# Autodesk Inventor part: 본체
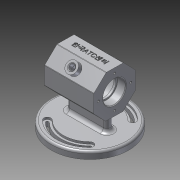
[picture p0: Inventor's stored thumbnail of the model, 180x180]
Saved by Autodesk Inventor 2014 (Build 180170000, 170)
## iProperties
Created: 2017-06
Part Number: 본체
Material: 알루미늄 6061
Document SubType Name: Modeling
Designer: Administrator
Density: 2.71 g/cm^3
Appearance: 알루미늄 - 평지
Mass: 555.742 g
Surface Area: 568.044 cm^2
Volume: 205.071 cm^3
Author: Administrator
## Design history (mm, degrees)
sketch "스케치1"
  geometry: C1 r 55 at (0, 0); 1 further point
  constraints: 1 centre point, 1 coincident
  dimensions: "d0" = 110 diameter of C1
extrude "돌출1" new body sketch "스케치1" distance "d1" = 10; taper "d2" = 0 deg
sketch "스케치2"
  geometry: L1 (0, 0)-(-33.941, 33.941); L2 (0, 0)-(48, 0); L3 (0, 0)-(33.941, 33.941); L4 (0, 0)-(48, 0); L5 (0, 0)-(-33.941, -33.941); L6 (0, 0)-(48, 0); L7 (0, 0)-(33.941, -33.941); L8 (0, 0)-(48, 0); C1 r 5 at (30.406, 30.406); C2 r 5 at (-30.406, -30.406); C3 r 5 at (30.406, -30.406); A1 r 38 centre (0, 0) between (-26.87, -26.87) and (26.87, -26.87); A2 r 38 centre (0, 0) between (26.87, 26.87) and (-26.87, 26.87); A3 r 48 centre (0, 0) between (-33.941, -33.941) and (33.941, -33.941); A4 r 48 centre (0, 0) between (33.941, 33.941) and (-33.941, 33.941); A5 r 5 centre (-30.406, 30.406) between (-33.941, 33.941) and (-26.87, 26.87)
  constraints: 16 end point, 10 point on circle, 8 centre point, 4 equal length, 4 horizontal, 4 point on line, 1 coincident
  dimensions: "d6" = 135 deg angle of L2 L1; "d7" = 45 deg angle of L4 L3; "d8" = 135 deg angle of L5 L6; "d9" = 45 deg angle of L7 L8; "d10" = 10 diameter of A5; "d11" = 10 diameter of C1; "d12" = 10 diameter of C2; "d13" = 10 diameter of C3
extrude "돌출2" cut sketch "스케치2" distance "d14" = 3; taper "d15" = 0 deg
sketch "스케치3"
  geometry: C1 r 55 at (0, 0) reference; A1 r 5 centre (-30.406, -30.406) between (-26.87, -26.87) and (-33.941, -33.941) reference; A2 r 5 centre (30.406, -30.406) between (33.941, -33.941) and (26.87, -26.87) reference; A3 r 5 centre (30.406, 30.406) between (26.87, 26.87) and (33.941, 33.941) reference; A4 r 5 centre (-30.406, 30.406) between (-33.941, 33.941) and (-26.87, 26.87) reference; A5 r 2 centre (-30.406, 30.406) between (-31.82, 31.82) and (-28.991, 28.991); A6 r 2 centre (30.406, 30.406) between (28.991, 28.991) and (31.82, 31.82); A7 r 2 centre (-30.406, -30.406) between (-28.991, -28.991) and (-31.82, -31.82); A8 r 41 centre (0, 0) between (-28.991, -28.991) and (28.991, -28.991); A9 r 41 centre (0, 0) between (28.991, 28.991) and (-28.991, 28.991); A10 r 45 centre (0, 0) between (-31.82, -31.82) and (31.82, -31.82); A11 r 45 centre (0, 0) between (31.82, 31.82) and (-31.82, 31.82); A12 r 2 centre (30.406, -30.406) between (28.991, -28.991) and (31.82, -31.82)
  constraints: 16 point on circle, 8 centre point, 6 coincident
  dimensions: "d16" = 4 diameter of A5; "d17" = 4 diameter of A6; "d18" = 4 diameter of A7; "d21" = 4 diameter of A12
extrude "돌출3" cut sketch "스케치3" stored distance "d22" = 3; taper "d23" = 0 deg
sketch "스케치4"
  geometry: L1 (24, 5)-(-24, 5); L2 (-24, 5)-(-24, -5); L3 (-24, -5)-(24, -5); L4 (24, -5)-(24, 5); L5 (24, 5)-(-24, -5); L6 (-24, 5)-(24, -5); C1 r 55 at (0, 0) reference; C2 r 5 at (-24, 0); C3 r 5 at (24, 0)
  constraints: 12 end point, 4 midpoint, 2 centre point, 2 parallel, 1 horizontal, 1 perpendicular
  dimensions: "d24" = 48 distance between parallel lines of L4 L2; "d25" = 10 distance between parallel lines of L3 L1; "d26" = 10 diameter of C2; "d27" = 10 diameter of C3
extrude "돌출4" join sketch "스케치4" distance "d28" = 52; taper "d29" = 0 deg
node "작업 평면1"
sketch "스케치5"
  geometry: L1 (38, 10)-(38, 7) reference; L2 (38, 7)-(41, 7) reference; L3 (41, 7)-(41, 0) reference; L4 (41, 0)-(-41, 0) reference; L5 (-41, 0)-(-41, 7) reference; L6 (-41, 7)-(-38, 7) reference; L7 (-38, 7)-(-38, 10) reference; L8 (-38, 10)-(-5, 10) reference; L9 (-5, 10)-(-5, 62) reference; L10 (-5, 62)-(5, 62) reference; L11 (5, 62)-(5, 10) reference; L12 (5, 10)-(38, 10) reference; L13 (-55, 0)-(-55, 10) reference; L14 (-55, 10)-(-48, 10) reference; L15 (-48, 10)-(-48, 7) reference; L16 (-48, 7)-(-45, 7) reference; L17 (-45, 7)-(-45, 0) reference; L18 (-45, 0)-(-55, 0) reference; L19 (55, 10)-(55, 0) reference; L20 (55, 0)-(45, 0) reference; L21 (45, 0)-(45, 7) reference; L22 (45, 7)-(48, 7) reference; L23 (48, 7)-(48, 10) reference; L24 (48, 10)-(55, 10) reference; L25 (-11.904, 92)-(12.795, 91.631); L26 (12.795, 91.631)-(30, 73.904); L27 (30, 73.904)-(29.631, 49.205); L28 (29.631, 49.205)-(11.904, 32); L29 (11.904, 32)-(-12.795, 32.369); L30 (-12.795, 32.369)-(-30, 50.096); L31 (-30, 50.096)-(-29.631, 74.795); L32 (-29.631, 74.795)-(-11.904, 92); 2 further points
  constraints: 16 end point, 17 other
extrude "돌출5" join sketch "스케치5" stored distance "d32" = 70; taper "d33" = 0 deg
node "작업 평면2"
sketch "스케치6"
  geometry: L1 (38, 10)-(38, 7) reference; L2 (38, 7)-(41, 7) reference; L3 (41, 7)-(41, 0) reference; L4 (41, 0)-(-41, 0) reference; L5 (-41, 0)-(-41, 7) reference; L6 (-41, 7)-(-38, 7) reference; L7 (-38, 7)-(-38, 10) reference; L8 (-38, 10)-(-5, 10) reference; L9 (-5, 10)-(-5, 32.253) reference; L10 (-5, 32.253)-(-12.795, 32.369) reference; L11 (-12.795, 32.369)-(-30, 50.096) reference; L12 (-30, 50.096)-(-29.631, 74.795) reference; L13 (-29.631, 74.795)-(-11.904, 92) reference; L14 (-11.904, 92)-(12.795, 91.631) reference; L15 (12.795, 91.631)-(30, 73.904) reference; L16 (30, 73.904)-(29.631, 49.205) reference; L17 (29.631, 49.205)-(11.904, 32) reference; L18 (11.904, 32)-(5, 32.103) reference; L19 (5, 32.103)-(5, 10) reference; L20 (5, 10)-(38, 10) reference; L21 (-55, 0)-(-55, 10) reference; L22 (-55, 10)-(-48, 10) reference; L23 (-48, 10)-(-48, 7) reference; L24 (-48, 7)-(-45, 7) reference; L25 (-45, 7)-(-45, 0) reference; L26 (-45, 0)-(-55, 0) reference; L27 (55, 10)-(55, 0) reference; L28 (55, 0)-(45, 0) reference; L29 (45, 0)-(45, 7) reference; L30 (45, 7)-(48, 7) reference; L31 (48, 7)-(48, 10) reference; L32 (48, 10)-(55, 10) reference; L33 (21.087, 40.913)-(-26.038, 88.038); L34 (-26.829, 77.515)-(-21.087, 83.087); L35 (-31.779, 82.465)-(-26.038, 88.038); L36 (15.346, 35.34)-(-31.779, 82.465); L37 (-31.779, 82.465)-(-5.657, 56.343); 1 further point
  constraints: 10 end point, 4 point on line, 2 parallel, 1 collinear
  dimensions: "d36" = 7 distance between parallel lines of L13 L35; "d108" = 8 distance between parallel lines of L37 L33
revolve "회전1" sketch "스케치6" stored, may be unused: angle "d38" = 90 deg
node "작업 평면3"
sketch "스케치7"
  geometry: L1 (-55, 0)-(-55, 10) reference; L2 (-55, 10)-(-29, 10) reference; L3 (-29, 10)-(-29, 32.178) reference; L4 (-29, 32.178)-(-35, 32.178) reference; L5 (-35, 32.178)-(-35, 91.822) reference; L6 (-35, 91.822)-(35, 91.822) reference; L7 (35, 91.822)-(35, 32.178) reference; L8 (35, 32.178)-(29, 32.178) reference; L9 (29, 32.178)-(29, 10) reference; L10 (29, 10)-(55, 10) reference; L11 (55, 10)-(55, 0) reference; L12 (55, 0)-(-55, 0) reference; L13 (-35, 62)-(35, 62); L14 (35, 78)-(23, 78); L15 (23, 78)-(23, 62); L16 (23, 76)-(20, 76); L17 (20, 76)-(20, 62); L18 (20, 76)-(20, 87); L19 (20, 87)-(-20, 87); L20 (-20, 87)-(-20, 62); L21 (-20, 76)-(-23, 76); L22 (-23, 76)-(-23, 62); L23 (-23, 76)-(-23, 78); L24 (-23, 78)-(-35, 78); L25 (20, 76)-(20, 87); L26 (-23, 76)-(-23, 78); 1 further point
  constraints: 28 end point, 8 perpendicular, 8 point on line, 3 collinear, 2 midpoint, 2 parallel
  dimensions: "d40" = 32 diameter of L14 L13; "d41" = 32 diameter of L24 L13; "d42" = 28 diameter of L16 L13; "d43" = 28 diameter of L21 L13; "d44" = 12 distance between parallel lines of L7 L15; "d45" = 12 distance between parallel lines of L22 L5; "d46" = 3 distance between parallel lines of L20 L22; "d47" = 3 distance between parallel lines of L15 L17; "d48" = 50 diameter of L19 L13
revolve "회전2" sketch "스케치7" stored, may be unused: angle "d49" = 90 deg
sketch "스케치8"
  geometry: L1 (70, 42.17)-(0, 42.17) reference; 2 further points
  constraints: 1 other
  dimensions: "d52" = 35 horizontal distance of point (35, 12.17) L1.end; "d53" = 30 distance from line of point (35, 12.17) L1
feature "엠보싱1" sketch "스케치8" dims "d2" = 0, "d54" = 0.5, "d55" = 0
fillet "모깎기1" dims "d56" = 3
fillet "모깎기2" dims "d57" = 5
chamfer "모따기1" distance "d58" = 1; stored, may be unused: second distance "d59" = 2, angle "d60" = 45 deg
fillet "모깎기3" dims "d61" = 3
fillet "모깎기4" dims "d62" = 0.3
node "작업 평면4"
node "작업 평면5"
sketch "스케치11" dims "d89" = 46
  geometry: L1 (62, 0)-(108.67, 0); L2 (62, 0)-(105.085, 17.846); C1 r 17 at (62, 0) reference; 3 further points
  constraints: 4 end point, 2 coincident, 1 horizontal, 1 horizontal alignment, 1 point on line, 2 other
  dimensions: "d90" = 22.5 deg angle of L1 L2
hole "구멍3" sketch "스케치11" at (85, 0) diameter "d91" = 3.242; stored, may be unused: countersink angle "d95" = 90 deg, drill point angle "d97" = 118 deg; dims "d92" = 8, "d93" = 4, "d94" = 2, "d96" = 10
node "작업 평면6"
node "작업 평면7"
sketch "스케치12"
  geometry: L1 (35, 3.8)-(35, 11.801) reference; C1 r 4 at (35, 11.801); 2 further points; 1 other entity
  constraints: 1 centre point, 1 coincident, 1 vertical alignment
  dimensions: "d102" = 8 diameter of C1
extrude "돌출7" cut sketch "스케치12" stored distance "d103" = 70; taper "d104" = 0 deg
chamfer "모따기3" distance "d105" = 1; stored, may be unused: second distance "d106" = 2, angle "d107" = 45 deg
fillet "모깎기6" dims "d112" = 1
node "솔리드1"
pattern_circular "원형 패턴1" dims angle "d99" = 360 deg
mirror "대칭1"
node "절단 모서리 투영1"
node "절단 모서리 투영2"
node "절단 모서리 투영3"
node "절단 모서리 투영6"
other parameters: "d3" = 86, "d4" = 96, "d5" = 76, "d20" = 82, "d30" = 0, "d34" = 0, "d37" = 8, "d39" = 0, "d72" = 7, "d80" = 7, "d101" = 7
